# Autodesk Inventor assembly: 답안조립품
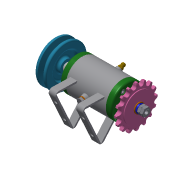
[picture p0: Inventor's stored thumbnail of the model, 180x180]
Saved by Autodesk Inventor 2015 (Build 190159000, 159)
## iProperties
Created: 2021-12
Part Number: 답안조립품
Document SubType Name: Assembly
Designer: pc-04
Author: pc-04
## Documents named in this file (15)
- C:\Users\pc-04\Desktop\711206V1019\답안조립품.iam
- C:\Users\pc-04\Desktop\711206V1019\본체.ipt
- C:\Users\pc-04\Desktop\711206V1019\축.ipt
- C:\Users\pc-04\Desktop\711206V1019\스프로킷.ipt
- C:\Users\pc-04\Desktop\711206V1019\커버.ipt
- C:\Users\pc-04\Desktop\711206V1019\V벨트풀리.ipt
- C:\Users\pc-04\Desktop\711206V1019\베어링 6002.ipt
- C:\Users\pc-04\Desktop\711206V1019\키 3 x 3.ipt
- C:\Users\pc-04\Desktop\711206V1019\와셔 8 x 17.ipt
- C:\Users\pc-04\Desktop\711206V1019\스프링와셔 8.ipt
- C:\Users\pc-04\Desktop\711206V1019\너트 M8.ipt
- C:\Users\pc-04\Desktop\711206V1019\니플 M6 x 0.75.ipt
- C:\Users\pc-04\Desktop\711206V1019\볼트 M4 x 12.ipt
- C:\Users\pc-04\Desktop\711206V1019\와셔 6 x 11.5.ipt
- C:\Users\pc-04\Desktop\711206V1019\볼트 M6 x 8.ipt
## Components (11 placed, 3 different names)
1. V벨트풀리:1
2. KS B 2023 6002 - 15 x 32 x 9:1
3. KS B 2023 6002 - 15 x 32 x 9:2
4. ISO 4762 M4 x 12:1
5. ISO 4762 M4 x 12:2
6. ISO 4762 M4 x 12:3
7. ISO 4762 M4 x 12:4
8. ISO 4762 M4 x 12:5
9. ISO 4762 M4 x 12:6
10. ISO 4762 M4 x 12:7
11. ISO 4762 M4 x 12:8
